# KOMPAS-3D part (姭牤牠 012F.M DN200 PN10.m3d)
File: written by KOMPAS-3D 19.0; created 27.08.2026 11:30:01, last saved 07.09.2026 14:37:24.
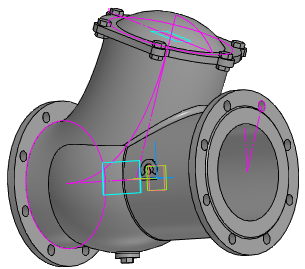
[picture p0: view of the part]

Document properties: Автор: Энергия; Полное имя файла: Z:\3.Личные\kachalov\001_3d для проектировщиков\х.х Тип 012F\012F.M\Клапан 012F.M DN200 PN10.m3d

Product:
- Part/product: (unnamed)  | designation Клапан 012F.M DN200 PN10
    Масса: 204.43

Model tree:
1. Эскиз:1
2. Элемент вращения:1
     Угол 1 = 360
3. Эскиз:2  (with: Элемент вращения:1)
4. Перпендикулярная плоскость:1
5. Эскиз:3
6. Эскиз:12  (with: Элемент вращения:1)
7. Элемент по сечениям:1
8. Эскиз:7
9. Элемент выдавливания:2
     Расстояние 2 = 15
10. Эскиз:9  (with: Элемент выдавливания:2)
11. Элемент вращения:2
     Угол 1 = 360
12. Эскиз:10  (with: Элемент вращения:1)
13. Элемент выдавливания:3  (with: Элемент вращения:1)
     Расстояние 2 = 17
14. Массив по концентрической сетке:1  (with: Элемент выдавливания:3, Эскиз:10, Элемент вращения:1)  (8 pattern instances)
     Шаг 2 = 360
15. Эскиз:11  (with: Элемент вращения:1)
16. Элемент выдавливания:4  (with: Элемент вращения:1)
     Расстояние 2 = 17
17. Массив по концентрической сетке:2  (with: Элемент выдавливания:4, Эскиз:11, Элемент вращения:1)  (8 pattern instances)
     Шаг 2 = 360
18. Скругление:6  (with: Элемент выдавливания:2)
     Радиус = 3
19. Эскиз:13  (with: Элемент выдавливания:2)
20. Элемент выдавливания:5  (with: Элемент выдавливания:2)
     Расстояние 1 = 10; Смещение 2 = 10
21. Массив по концентрической сетке:3  (with: Элемент выдавливания:5, Эскиз:9, Эскиз:13, Элемент вращения:2)  (6 pattern instances)
     Шаг 2 = 360
22. Касательная плоскость:1  (with: Элемент вращения:1)
     Угол = 90
23. Смещенная плоскость:1
     Расстояние = 2
24. Эскиз:14
25. Элемент выдавливания:6  (with: Элемент вращения:1)
     Расстояние 1 = -2.24729; Расстояние 2 = 1
26. Эскиз:15  (with: Элемент вращения:1)
27. Элемент вращения:3  (with: Элемент вращения:1)
     Угол 1 = 360
28. Скругление:10  (with: Элемент вращения:3, Элемент по сечениям:1)
     Радиус = 10
29. Эскиз:16
30. Элемент выдавливания:7
     Расстояние 1 = 160
31. Эскиз:17  (with: Элемент выдавливания:7)
32. Элемент выдавливания:8
     Расстояние 1 = 10
33. Эскиз:18  (with: Элемент вращения:1)
34. Элемент выдавливания:9
     Расстояние 2 = 500
35. Скругление:12  (with: Элемент выдавливания:7)
     Радиус = 3

Expressions: Dn/2; D/2; D2/2; D2/2-5; 360/(2*n); 360/(n*2); D2-6; D2-5; 340/2
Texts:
  Клапан 012F.M DN200 PN10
